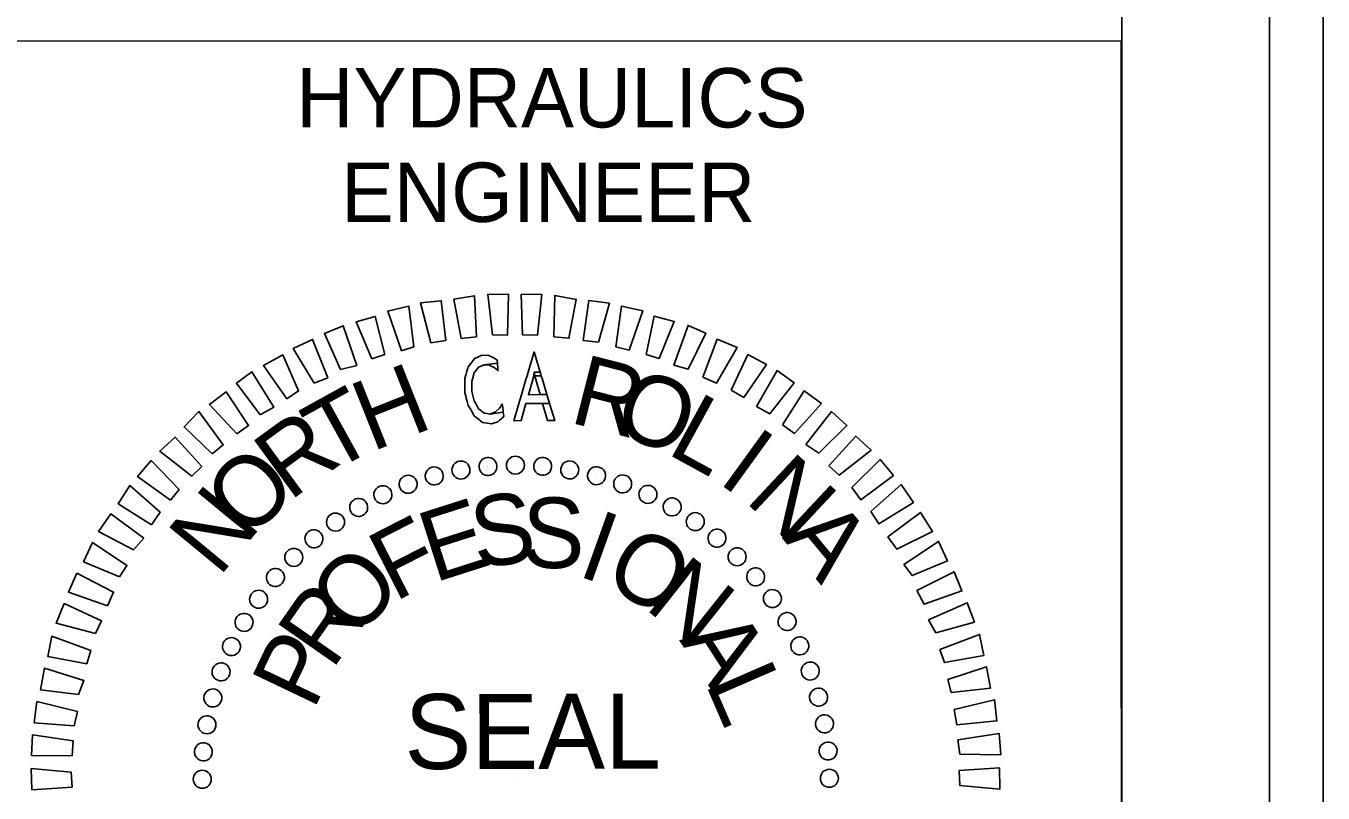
# Model space of a CAD drawing. Extents: x 2568837 to 2570520, y 536545 to 537640.
# Drawn here: x 2570410.9 to 2570520.2, y 537516.2 to 537580.9 of the extents above; entities that cross this region are included whole.
import ezdxf

# ---------------------------------------------------------------- set-up
doc = ezdxf.new("R2010")
doc.units = 0
for name, color, linetype in [('Default', 7, 'Continuous'), ('Sheet Plan CELL', 7, 'Continuous'), ('Sheet Plan Layout CELL', 7, 'Continuous'), ('Sheet Plot Border Inside CELL', 7, 'Continuous'), ('Sheet Plot Border Outside CELL', 7, 'Continuous')]:
    doc.layers.add(name, color=color, linetype=linetype)

msp = doc.modelspace()

# ---------------------------------------------------------------- linework, layer by layer
at = {"layer": 'Default'}
for p, q in [((2570445.25, 537542.95), (2570445.25, 537542.95)), ((2570445.25, 537542.95), (2570445.25, 537542.95)), ((2570447.51, 537543.41), (2570447.51, 537543.41)), ((2570447.51, 537543.41), (2570447.51, 537543.41)), ((2570449.77, 537543.77), (2570449.77, 537543.77)), ((2570449.77, 537543.77), (2570449.77, 537543.77)), ((2570452.09, 537543.86), (2570452.09, 537543.86)), ((2570452.09, 537543.86), (2570452.09, 537543.86)), ((2570454.41, 537543.75), (2570454.41, 537543.75)), ((2570454.41, 537543.75), (2570454.41, 537543.75)), ((2570456.68, 537543.42), (2570456.68, 537543.42)), ((2570456.68, 537543.42), (2570456.68, 537543.42)), ((2570458.95, 537542.99), (2570458.95, 537542.99)), ((2570458.95, 537542.99), (2570458.95, 537542.99)), ((2570443.05, 537542.27), (2570443.05, 537542.27)), ((2570443.05, 537542.27), (2570443.05, 537542.27)), ((2570461.18, 537542.3), (2570461.18, 537542.3)), ((2570461.18, 537542.3), (2570461.18, 537542.3)), ((2570440.91, 537541.39), (2570440.91, 537541.39)), ((2570440.91, 537541.39), (2570440.91, 537541.39)), ((2570463.25, 537541.39), (2570463.25, 537541.39)), ((2570463.25, 537541.39), (2570463.25, 537541.39)), ((2570438.93, 537540.3), (2570438.93, 537540.3)), ((2570438.93, 537540.3), (2570438.93, 537540.3)), ((2570465.38, 537540.37), (2570465.38, 537540.37)), ((2570465.38, 537540.37), (2570465.38, 537540.37)), ((2570436.9, 537539.05), (2570436.9, 537539.05)), ((2570436.9, 537539.05), (2570436.9, 537539.05)), ((2570467.24, 537539.09), (2570467.24, 537539.09)), ((2570467.24, 537539.09), (2570467.24, 537539.09)), ((2570435.13, 537537.7), (2570435.13, 537537.7)), ((2570435.13, 537537.7), (2570435.13, 537537.7)), ((2570469.17, 537537.71), (2570469.17, 537537.71)), ((2570469.17, 537537.71), (2570469.17, 537537.71)), ((2570433.42, 537536.08), (2570433.42, 537536.08)), ((2570433.42, 537536.08), (2570433.42, 537536.08)), ((2570470.83, 537536.15), (2570470.83, 537536.15)), ((2570470.83, 537536.15), (2570470.83, 537536.15)), ((2570431.87, 537534.42), (2570431.87, 537534.42)), ((2570431.87, 537534.42), (2570431.87, 537534.42)), ((2570472.45, 537534.39), (2570472.45, 537534.39)), ((2570472.45, 537534.39), (2570472.45, 537534.39)), ((2570430.43, 537532.55), (2570430.43, 537532.55)), ((2570430.43, 537532.55), (2570430.43, 537532.55)), ((2570473.8, 537532.63), (2570473.8, 537532.63)), ((2570473.8, 537532.63), (2570473.8, 537532.63)), ((2570429.15, 537530.63), (2570429.15, 537530.63)), ((2570429.15, 537530.63), (2570429.15, 537530.63)), ((2570475.04, 537530.65), (2570475.04, 537530.65)), ((2570475.04, 537530.65), (2570475.04, 537530.65)), ((2570428.14, 537528.55), (2570428.14, 537528.55)), ((2570428.14, 537528.55), (2570428.14, 537528.55)), ((2570476.09, 537528.62), (2570476.09, 537528.62)), ((2570476.09, 537528.62), (2570476.09, 537528.62)), ((2570476.97, 537526.52), (2570476.97, 537526.52)), ((2570476.97, 537526.52), (2570476.97, 537526.52)), ((2570427.23, 537526.43), (2570427.23, 537526.43)), ((2570427.23, 537526.43), (2570427.23, 537526.43)), ((2570477.7, 537524.32), (2570477.7, 537524.32)), ((2570477.7, 537524.32), (2570477.7, 537524.32)), ((2570426.53, 537524.2), (2570426.53, 537524.2)), ((2570426.53, 537524.2), (2570426.53, 537524.2)), ((2570426.1, 537521.98), (2570426.1, 537521.98)), ((2570426.1, 537521.98), (2570426.1, 537521.98)), ((2570478.16, 537522.01), (2570478.16, 537522.01)), ((2570478.16, 537522.01), (2570478.16, 537522.01)), ((2570425.83, 537519.66), (2570425.83, 537519.66)), ((2570425.83, 537519.66), (2570425.83, 537519.66)), ((2570478.52, 537519.76), (2570478.52, 537519.76)), ((2570478.52, 537519.76), (2570478.52, 537519.76)), ((2570425.71, 537517.34), (2570425.71, 537517.34)), ((2570425.71, 537517.34), (2570425.71, 537517.34)), ((2570452.17, 537517.41), (2570452.17, 537517.41)), ((2570452.17, 537517.41), (2570452.17, 537517.41)), ((2570478.61, 537517.44), (2570478.61, 537517.44)), ((2570478.61, 537517.44), (2570478.61, 537517.44))]:
    msp.add_line(p, q, dxfattribs=at)
for points in [[(2570450.2, 537554.84), (2570449.81, 537558.26), (2570451.55, 537558.24), (2570451.46, 537554.81)], [(2570452.72, 537554.84), (2570452.61, 537558.26), (2570454.34, 537558.24), (2570453.99, 537554.81)], [(2570442.52, 537553.48), (2570441.36, 537556.83), (2570443.14, 537557.24), (2570443.57, 537553.82)], [(2570444.99, 537554.16), (2570444.13, 537557.52), (2570445.87, 537557.71), (2570446.25, 537554.35)], [(2570447.56, 537554.53), (2570446.92, 537557.83), (2570448.66, 537558.13), (2570448.83, 537554.66)], [(2570455.36, 537554.67), (2570455.45, 537558.15), (2570457.25, 537557.82), (2570456.63, 537554.54)], [(2570457.84, 537554.35), (2570458.31, 537557.73), (2570460.05, 537557.5), (2570459.11, 537554.22)], [(2570460.59, 537553.83), (2570461.06, 537557.26), (2570462.85, 537556.87), (2570461.7, 537553.53)], [(2570440.01, 537552.81), (2570438.69, 537555.94), (2570440.31, 537556.39), (2570441.11, 537553.19)], [(2570463.13, 537553.19), (2570463.81, 537556.41), (2570465.5, 537555.97), (2570464.25, 537552.84)], [(2570437.39, 537551.91), (2570436.02, 537554.94), (2570437.59, 537555.6), (2570438.75, 537552.26)], [(2570465.47, 537552.28), (2570466.67, 537555.63), (2570468.16, 537554.97), (2570466.69, 537551.94)], [(2570435.15, 537550.76), (2570433.4, 537553.68), (2570435.02, 537554.45), (2570436.3, 537551.21)], [(2570467.91, 537551.28), (2570469.12, 537554.46), (2570470.82, 537553.76), (2570469.08, 537550.77)], [(2570432.85, 537549.45), (2570430.9, 537552.26), (2570432.52, 537553.14), (2570433.84, 537550.11)], [(2570449.73, 537547.39), (2570450.11, 537547.34), (2570450.64, 537547.51), (2570450.78, 537547.63), (2570450.99, 537547.8), (2570451.14, 537547.99), (2570451.1, 537548.3), (2570451.1, 537548.31), (2570449.97, 537548.16), (2570449.56, 537548.23), (2570449.49, 537548.24), (2570449.21, 537548.46), (2570449.02, 537548.61), (2570448.81, 537548.98), (2570448.65, 537549.28), (2570448.46, 537550.06), (2570448.46, 537550.06), (2570448.45, 537550.89), (2570448.53, 537551.22), (2570448.61, 537551.53), (2570448.63, 537551.6), (2570448.84, 537551.88), (2570449, 537552.1), (2570449.15, 537552.16), (2570449.48, 537552.3), (2570450.6, 537552.45), (2570450.6, 537552.45), (2570450.57, 537552.71), (2570450.3, 537552.9), (2570450.06, 537553.01), (2570449.87, 537553.1), (2570449.3, 537553.12), (2570449.01, 537552.98), (2570448.67, 537552.83), (2570448.55, 537552.68), (2570448.36, 537552.42), (2570448.13, 537552.13), (2570448.13, 537552.13), (2570448.11, 537552.03), (2570448.09, 537551.98), (2570448.04, 537551.78), (2570447.96, 537551.51), (2570447.94, 537551.45), (2570447.86, 537551.14), (2570447.86, 537550.81), (2570447.86, 537549.99), (2570447.86, 537549.98), (2570448.06, 537549.21), (2570448.14, 537548.89), (2570448.35, 537548.53), (2570448.44, 537548.36), (2570448.58, 537548.12), (2570448.59, 537548.1), (2570448.66, 537547.99), (2570448.66, 537547.98), (2570449, 537547.72), (2570449.2, 537547.57), (2570449.36, 537547.45)], [(2570452.42, 537549.04), (2570451.99, 537547.6), (2570452.6, 537547.61), (2570453.01, 537549.04), (2570455, 537549.04), (2570454.77, 537549.8), (2570453.22, 537549.79), (2570453.58, 537551.06), (2570453.58, 537551.06), (2570453.66, 537551.38), (2570453.66, 537551.39), (2570453.71, 537551.69), (2570454.21, 537551.69), (2570453.7, 537553.39), (2570453.2, 537551.69), (2570453.11, 537551.39), (2570453.11, 537551.38), (2570453.01, 537551.06), (2570453.01, 537551.06), (2570452.64, 537549.79)], [(2570470.31, 537550.16), (2570471.72, 537553.19), (2570473.27, 537552.32), (2570471.37, 537549.55)], [(2570430.61, 537548.1), (2570428.61, 537550.75), (2570429.91, 537551.72), (2570431.76, 537548.75)], [(2570450.6, 537551.85), (2570450.66, 537551.8), (2570450.65, 537551.86), (2570450.63, 537552.11), (2570450.61, 537552.3), (2570450.61, 537552.3), (2570450.61, 537552.35), (2570450.6, 537552.45), (2570449.48, 537552.3), (2570449.95, 537552.27), (2570450.03, 537552.23), (2570450.34, 537552.08)], [(2570453.71, 537551.69), (2570453.77, 537551.39), (2570454.3, 537551.39), (2570454.21, 537551.69)], [(2570472.44, 537548.78), (2570474.17, 537551.82), (2570475.61, 537550.79), (2570473.56, 537548.17)], [(2570453.85, 537551.06), (2570454.21, 537549.8), (2570454.77, 537549.8), (2570454.4, 537551.06), (2570454.39, 537551.06), (2570454.3, 537551.38), (2570454.3, 537551.39), (2570453.77, 537551.39), (2570453.77, 537551.38), (2570453.85, 537551.06)], [(2570428.64, 537546.48), (2570426.33, 537548.97), (2570427.73, 537550.04), (2570429.63, 537547.18)], [(2570474.63, 537547.24), (2570476.47, 537550.12), (2570477.91, 537549.04), (2570475.64, 537546.52)], [(2570450.45, 537548.34), (2570449.97, 537548.16), (2570451.1, 537548.31), (2570451.09, 537548.42), (2570451.08, 537548.44), (2570451.05, 537548.7), (2570451.03, 537548.87), (2570451.01, 537549), (2570451.01, 537549), (2570450.92, 537548.86), (2570450.79, 537548.66), (2570450.47, 537548.36)], [(2570454.41, 537549.04), (2570454.82, 537547.61), (2570455.43, 537547.61), (2570455, 537549.04)], [(2570476.61, 537545.59), (2570478.77, 537548.37), (2570480.06, 537547.19), (2570477.68, 537544.87)], [(2570426.57, 537544.8), (2570424.2, 537547.08), (2570425.44, 537548.37), (2570427.5, 537545.56)], [(2570424.86, 537542.93), (2570422.14, 537545.04), (2570423.43, 537546.22), (2570425.69, 537543.74)], [(2570478.54, 537543.78), (2570480.81, 537546.3), (2570482.1, 537545.12), (2570479.4, 537543.01)], [(2570423.06, 537540.89), (2570420.28, 537542.9), (2570421.41, 537544.23), (2570423.78, 537541.8)], [(2570480.47, 537541.98), (2570482.85, 537544.34), (2570483.98, 537542.99), (2570481.23, 537540.93)], [(2570421.46, 537538.81), (2570418.63, 537540.6), (2570419.61, 537542.14), (2570422.18, 537539.88)], [(2570482.09, 537539.95), (2570484.63, 537542.21), (2570485.66, 537540.7), (2570482.74, 537538.91)], [(2570419.92, 537536.72), (2570416.99, 537538.25), (2570418.02, 537539.74), (2570420.8, 537537.69)], [(2570483.5, 537537.82), (2570486.25, 537539.87), (2570487.28, 537538.26), (2570484.26, 537536.78)], [(2570418.75, 537534.43), (2570415.72, 537535.7), (2570416.48, 537537.34), (2570419.37, 537535.4)], [(2570484.86, 537535.47), (2570487.78, 537537.42), (2570488.54, 537535.8), (2570485.56, 537534.54)], [(2570417.74, 537531.99), (2570414.45, 537533.14), (2570415.16, 537534.74), (2570418.25, 537533.16)], [(2570485.96, 537533.28), (2570489.09, 537534.87), (2570489.75, 537533.25), (2570486.56, 537532.13)], [(2570416.74, 537529.66), (2570413.4, 537530.54), (2570414.1, 537532.19), (2570417.24, 537530.72)], [(2570486.95, 537530.82), (2570490.19, 537532.25), (2570490.8, 537530.63), (2570487.55, 537529.73)], [(2570415.99, 537527.11), (2570412.71, 537527.73), (2570413.05, 537529.43), (2570416.34, 537528.22)], [(2570487.9, 537528.31), (2570491.24, 537529.59), (2570491.59, 537527.8), (2570488.28, 537527.21)], [(2570415.3, 537524.52), (2570412.08, 537524.93), (2570412.42, 537526.73), (2570415.75, 537525.69)], [(2570488.57, 537525.79), (2570491.82, 537526.86), (2570492.17, 537525.07), (2570488.86, 537524.7)], [(2570414.93, 537521.87), (2570411.56, 537522.13), (2570411.79, 537523.93), (2570415.22, 537523.09)], [(2570489.1, 537523.27), (2570492.5, 537524.08), (2570492.7, 537522.29), (2570489.33, 537521.96)], [(2570414.77, 537519.34), (2570411.34, 537519.38), (2570411.42, 537521.13), (2570414.85, 537520.61)], [(2570489.41, 537520.7), (2570492.88, 537521.24), (2570493.02, 537519.45), (2570489.59, 537519.49)], [(2570414.76, 537516.71), (2570411.35, 537516.49), (2570411.31, 537518.28), (2570414.69, 537517.97)], [(2570489.51, 537518.12), (2570492.93, 537518.34), (2570492.96, 537516.55), (2570489.59, 537516.86)]]:
    msp.add_lwpolyline(points, close=True, dxfattribs=at)
for centre, major_axis in [((2570447.53, 537543.44), (-0.133, 0.747)), ((2570449.81, 537543.74), (-0.067, 0.756)), ((2570452.12, 537543.85), (-0.001, 0.759)), ((2570454.42, 537543.75), (0.065, 0.756)), ((2570456.7, 537543.45), (0.131, 0.747)), ((2570443.08, 537542.24), (-0.26, 0.713)), ((2570445.28, 537542.94), (-0.197, 0.733)), ((2570458.96, 537542.96), (0.195, 0.733)), ((2570461.16, 537542.27), (0.258, 0.713)), ((2570440.95, 537541.36), (-0.322, 0.687)), ((2570463.29, 537541.39), (0.32, 0.688)), ((2570438.91, 537540.29), (-0.38, 0.656)), ((2570465.33, 537540.33), (0.378, 0.658)), ((2570436.96, 537539.05), (-0.436, 0.621)), ((2570467.28, 537539.09), (0.434, 0.622)), ((2570469.11, 537537.69), (0.487, 0.582)), ((2570435.14, 537537.64), (-0.488, 0.58)), ((2570433.44, 537536.08), (-0.537, 0.536)), ((2570470.81, 537536.13), (0.536, 0.537)), ((2570472.37, 537534.44), (0.58, 0.488)), ((2570431.89, 537534.38), (-0.582, 0.487)), ((2570430.48, 537532.55), (-0.622, 0.434)), ((2570473.78, 537532.61), (0.621, 0.436)), ((2570429.25, 537530.6), (-0.658, 0.378)), ((2570475.02, 537530.67), (0.656, 0.38)), ((2570428.19, 537528.56), (-0.688, 0.32)), ((2570476.09, 537528.62), (0.687, 0.322)), ((2570427.31, 537526.43), (-0.713, 0.258)), ((2570476.97, 537526.5), (0.713, 0.26)), ((2570426.62, 537524.23), (-0.733, 0.195)), ((2570477.67, 537524.3), (0.733, 0.197)), ((2570426.12, 537521.97), (-0.747, 0.131)), ((2570478.17, 537522.05), (0.747, 0.133)), ((2570425.82, 537519.69), (-0.756, 0.065)), ((2570478.47, 537519.76), (0.756, 0.067)), ((2570425.73, 537517.38), (-0.759, -0.001)), ((2570478.58, 537517.46), (0.759, 0.001))]:
    msp.add_ellipse(centre, major_axis=major_axis, ratio=0.999708, dxfattribs=at)
at = {"layer": 'Sheet Plan CELL'}
for points in [[(2570503.22, 537617.15), (2569003.18, 537617.15), (2569003.18, 536567.15), (2570503.19, 536567.15)], [(2570403.19, 537579.59), (2570503.18, 537579.6), (2570503.19, 537467.09), (2570403.19, 537467.08)]]:
    msp.add_lwpolyline(points, close=True, dxfattribs=at)
at = {"layer": 'Sheet Plan Layout CELL'}
msp.add_lwpolyline([(2570263.93, 537405.66), (2570503.2, 537405.66), (2570503.23, 537617.15), (2570263.93, 537617.15)], close=True, dxfattribs=at)
at = {"layer": 'Sheet Plot Border Inside CELL'}
msp.add_lwpolyline([(2568849.69, 536564.64), (2570515.68, 536564.65), (2570515.69, 537619.64), (2568849.69, 537619.64)], close=True, dxfattribs=at)
at = {"layer": 'Sheet Plot Border Outside CELL'}
msp.add_lwpolyline([(2568836.69, 536544.64), (2570520.19, 536544.64), (2570520.19, 537639.64), (2568836.69, 537639.64)], close=True, dxfattribs=at)

# ---------------------------------------------------------------- texts
at = {"layer": 'Default'}
for s, height, rotation, p in [('R', 5.94, 345.7021, (2570456.55, 537547.48)), ('H', 5.94, 21.7004, (2570440, 537544.95)), ('O', 5.94, 338.5021, (2570460.09, 537546.75)), ('T', 5.94, 28.9007, (2570436.55, 537543.15)), ('L', 5.94, 331.3018, (2570464.76, 537544.89)), ('R', 5.94, 36.1015, (2570433.07, 537540.76)), ('I', 5.94, 324.1011, (2570469.08, 537542.45)), ('O', 5.94, 43.3027, (2570429.5, 537537.43)), ('N', 5.94, 316.8999, (2570471.37, 537540.85)), ('N', 5.94, 50.5045, (2570427.13, 537534.33)), ('E', 5.94, 17.692, (2570445.26, 537533.93)), ('S', 5.94, 8.3366, (2570448.83, 537535.11)), ('S', 5.94, 358.9814, (2570452.62, 537535.23)), ('F', 5.94, 27.048, (2570441.92, 537532.29)), ('I', 5.94, 340.2706, (2570457.21, 537534.58)), ('A', 5.94, 309.6981, (2570474.54, 537537.75)), ('A', 5.94, 309.6981, (2570474.54, 537537.75)), ('O', 5.94, 330.9144, (2570459.33, 537533.88)), ('O', 5.94, 45.7622, (2570438.51, 537529.06)), ('N', 5.94, 321.5576, (2570462.9, 537531.84)), ('R', 5.94, 55.1206, (2570436.66, 537526.5)), ('A', 5.94, 302.8412, (2570465.9, 537529.11)), ('P', 5.94, 64.4798, (2570435.09, 537523.1)), ('L', 5.94, 293.4818, (2570468.08, 537525.51)), ('SEAL', 6.32, 0.081, (2570442.77, 537518.24))]:
    msp.add_text(s, height=height, rotation=rotation, dxfattribs=at).set_placement(p)
at = {"layer": 'Sheet Plan CELL'}
for s, p in [('HYDRAULICS', (2570433.65, 537572.31)), ('ENGINEER', (2570437.42, 537564.35))]:
    msp.add_text(s, height=5, rotation=0, dxfattribs=at).set_placement(p)

doc.saveas('drawing.dxf')
